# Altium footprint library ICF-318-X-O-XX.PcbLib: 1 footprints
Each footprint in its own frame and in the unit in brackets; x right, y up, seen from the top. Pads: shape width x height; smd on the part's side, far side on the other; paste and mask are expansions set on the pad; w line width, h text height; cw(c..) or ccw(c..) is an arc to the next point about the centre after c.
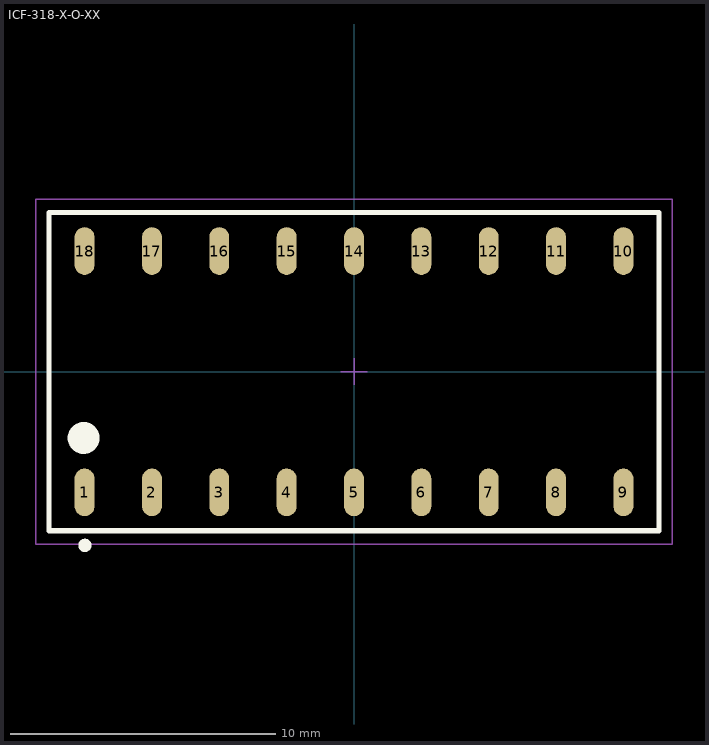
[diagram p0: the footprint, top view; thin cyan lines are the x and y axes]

## ICF-318-X-O-XX [mm] "2.54mm pitch, 18 pin, dip socket; 7.62mm LS"
height 4.57
pads (18):
  oval 0.75x1.8 smd mask+0: 1(-10.16,-4.55) 2(-7.62,-4.55) 3(-5.08,-4.55) 4(-2.54,-4.55) 5(0,-4.55) 6(2.54,-4.55) 7(5.08,-4.55) 8(7.62,-4.55) 9(10.16,-4.55) 10(10.16,4.55) 11(7.62,4.55) 12(5.08,4.55) 13(2.54,4.55) 14(0,4.55) 15(-2.54,4.55) 16(-5.08,4.55) 17(-7.62,4.55) 18(-10.16,4.55)
Top Overlay:
  circle w0.6: c-10.2,-2.5 r0.3
  circle w0.25: c-10.15,-6.55 r0.125
  lines w0.2: -11.5,-6 11.5,-6 11.5,6 -11.5,6 -11.5,-6
Mechanical 12:
  lines w0.001: -11.5,-6 11.5,-6 11.5,6 -11.5,6 -11.5,-6
Mechanical 13:
  circle w0.1: c-10.2,-2.5 r0.5
  lines w0.1: -11.5,-6 11.5,-6 11.5,6 -11.5,6 -11.5,-6
  text ".Designator" at 0.254,0.254 h1.52
Mechanical 15:
  lines w0.05: -0.5,0 0.5,0 ; 0,-0.5 0,0.5 ; -12,-6.5 -12,6.5 12,6.5 12,-6.5 -12,-6.5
